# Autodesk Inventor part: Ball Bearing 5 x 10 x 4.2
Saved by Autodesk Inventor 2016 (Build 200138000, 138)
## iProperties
Created: 2015-11
Part Number: Ball Bearing 5 x 10 x 4.2
Material: Generic
Document SubType Name: Modeling
Designer: John
Density: 1 g/cm^3
Appearance: Default
Author: John
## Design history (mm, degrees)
feature "SOLID1"
body "Solid1"
